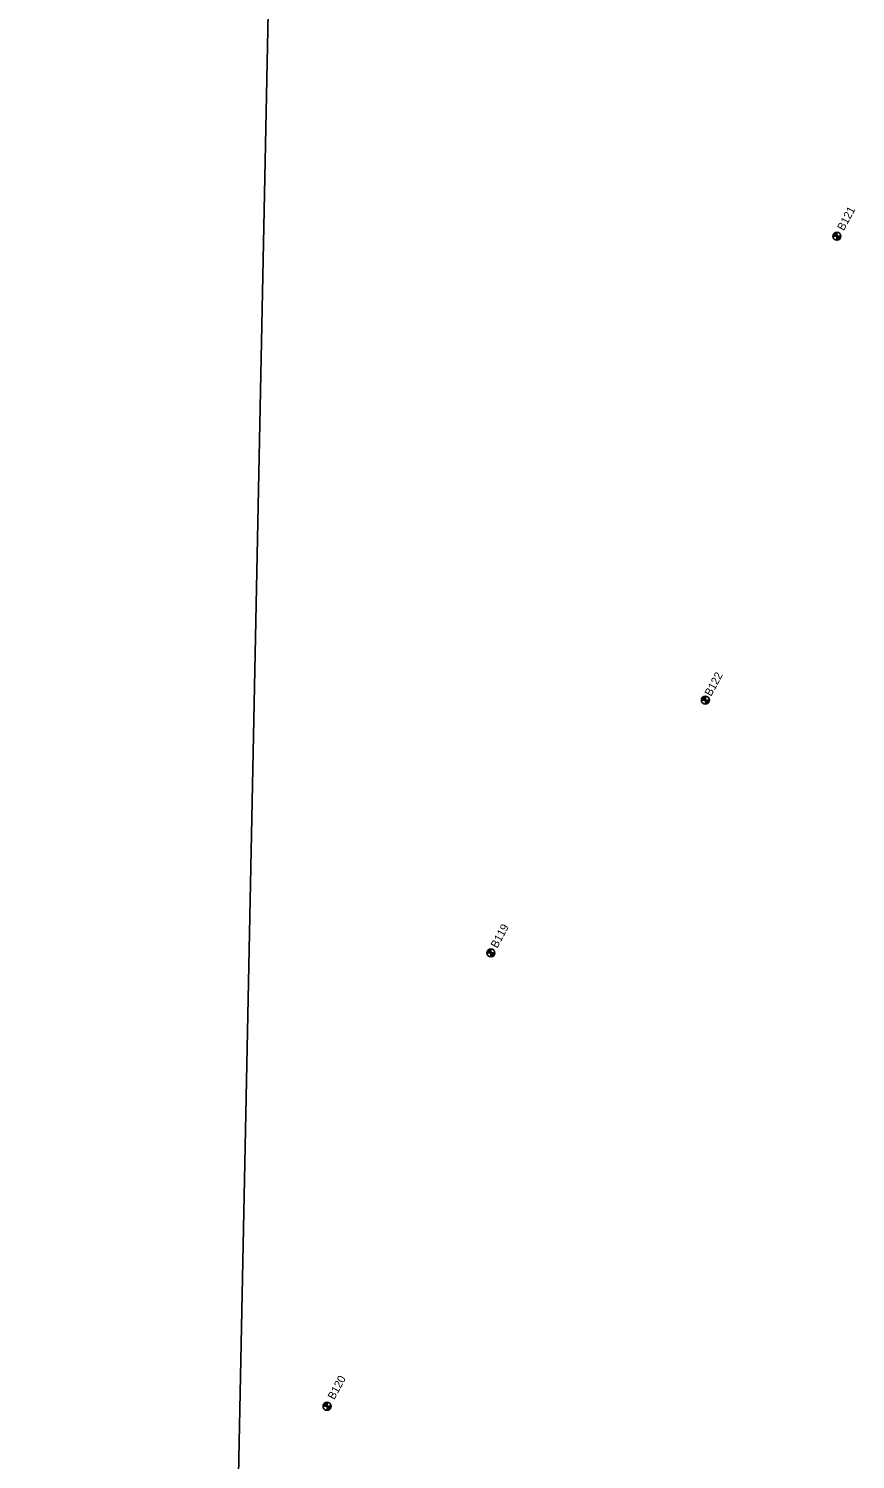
# Model space of a CAD drawing. Extents: x 345549 to 379569, y 127949 to 230467.
# Drawn here: x 355372 to 356405, y 194223 to 196011 of the extents above; entities that cross this region are included whole.
import ezdxf

# ---------------------------------------------------------------- set-up
doc = ezdxf.new("R2010")
doc.units = 0
for name, color, linetype in [('E_RDWY', 7, 'Continuous'), ('E_SOIL_BORE1 [KAPUR_CADDS_LEVELS]', 7, 'Continuous'), ('E_SOIL_BORE2 [KAPUR_CADDS_LEVELS]', 7, 'Continuous'), ('P_MARK', 7, 'Continuous')]:
    doc.layers.add(name, color=color, linetype=linetype)

msp = doc.modelspace()

# ---------------------------------------------------------------- linework, layer by layer
at = {"layer": 'E_RDWY'}
msp.add_line((355372.5, 181177.5), (356094.5, 217027.6), dxfattribs=at)
at = {"layer": 'P_MARK'}
for p, q in [((356377.4, 195752), (356387.4, 195752)), ((356382.4, 195757), (356382.4, 195747)), ((356213, 195172.4), (356223, 195172.4)), ((356218, 195177.4), (356218, 195167.4)), ((355945.1, 194856.3), (355955.1, 194856.3)), ((355950.1, 194861.3), (355950.1, 194851.3)), ((355740.3, 194289.7), (355750.3, 194289.7)), ((355745.3, 194294.7), (355745.3, 194284.7))]:
    msp.add_line(p, q, dxfattribs=at)
for centre in [(356382.4, 195752), (356218, 195172.4), (355950.1, 194856.3), (355745.3, 194289.7)]:
    msp.add_circle(centre, 5, dxfattribs=at)
for centre, radius, start, end in [((356382.4, 195752), 4.5, 89.9869, 179.9869), ((356382.4, 195752), 4, 89.9869, 179.9869), ((356382.4, 195752), 3.5, 89.9869, 179.9869), ((356382.4, 195752), 3, 89.9869, 179.9869), ((356382.4, 195752), 2.5, 89.9869, 179.9869), ((356382.4, 195752), 2, 89.9869, 179.9869), ((356382.4, 195752), 1.5, 89.9869, 179.9869), ((356382.4, 195752), 1, 89.9869, 179.9869), ((356382.4, 195752), 0.5, 89.9869, 179.9869), ((356382.4, 195752), 4.5, 269.9869, 359.9869), ((356382.4, 195752), 4, 269.9869, 359.9869), ((356382.4, 195752), 3.5, 269.9869, 359.9869), ((356382.4, 195752), 3, 269.9869, 359.9869), ((356382.4, 195752), 2.5, 269.9869, 359.9869), ((356382.4, 195752), 2, 269.9869, 359.9869), ((356382.4, 195752), 1.5, 269.9869, 359.9869), ((356382.4, 195752), 1, 269.9869, 359.9869), ((356382.4, 195752), 0.5, 269.9869, 359.9869), ((356218, 195172.4), 4.5, 89.9869, 179.9869), ((356218, 195172.4), 4, 89.9869, 179.9869), ((356218, 195172.4), 3.5, 89.9869, 179.9869), ((356218, 195172.4), 3, 89.9869, 179.9869), ((356218, 195172.4), 2.5, 89.9869, 179.9869), ((356218, 195172.4), 2, 89.9869, 179.9869), ((356218, 195172.4), 1.5, 89.9869, 179.9869), ((356218, 195172.4), 1, 89.9869, 179.9869), ((356218, 195172.4), 0.5, 89.9869, 179.9869), ((356218, 195172.4), 4.5, 269.9869, 359.9869), ((356218, 195172.4), 4, 269.9869, 359.9869), ((356218, 195172.4), 3.5, 269.9869, 359.9869), ((356218, 195172.4), 3, 269.9869, 359.9869), ((356218, 195172.4), 2.5, 269.9869, 359.9869), ((356218, 195172.4), 2, 269.9869, 359.9869), ((356218, 195172.4), 1.5, 269.9869, 359.9869), ((356218, 195172.4), 1, 269.9869, 359.9869), ((356218, 195172.4), 0.5, 269.9869, 359.9869), ((355950.1, 194856.3), 4.5, 89.9869, 179.9869), ((355950.1, 194856.3), 4, 89.9869, 179.9869), ((355950.1, 194856.3), 3.5, 89.9869, 179.9869), ((355950.1, 194856.3), 3, 89.9869, 179.9869), ((355950.1, 194856.3), 2.5, 89.9869, 179.9869), ((355950.1, 194856.3), 2, 89.9869, 179.9869), ((355950.1, 194856.3), 1.5, 89.9869, 179.9869), ((355950.1, 194856.3), 1, 89.9869, 179.9869), ((355950.1, 194856.3), 0.5, 89.9869, 179.9869), ((355950.1, 194856.3), 4.5, 269.9869, 359.9869), ((355950.1, 194856.3), 4, 269.9869, 359.9869), ((355950.1, 194856.3), 3.5, 269.9869, 359.9869), ((355950.1, 194856.3), 3, 269.9869, 359.9869), ((355950.1, 194856.3), 2.5, 269.9869, 359.9869), ((355950.1, 194856.3), 2, 269.9869, 359.9869), ((355950.1, 194856.3), 1.5, 269.9869, 359.9869), ((355950.1, 194856.3), 1, 269.9869, 359.9869), ((355950.1, 194856.3), 0.5, 269.9869, 359.9869), ((355745.3, 194289.7), 4.5, 89.9869, 179.9869), ((355745.3, 194289.7), 4, 89.9869, 179.9869), ((355745.3, 194289.7), 3.5, 89.9869, 179.9869), ((355745.3, 194289.7), 3, 89.9869, 179.9869), ((355745.3, 194289.7), 2.5, 89.9869, 179.9869), ((355745.3, 194289.7), 2, 89.9869, 179.9869), ((355745.3, 194289.7), 1.5, 89.9869, 179.9869), ((355745.3, 194289.7), 1, 89.9869, 179.9869), ((355745.3, 194289.7), 0.5, 89.9869, 179.9869), ((355745.3, 194289.7), 4.5, 269.9869, 359.9869), ((355745.3, 194289.7), 4, 269.9869, 359.9869), ((355745.3, 194289.7), 3.5, 269.9869, 359.9869), ((355745.3, 194289.7), 3, 269.9869, 359.9869), ((355745.3, 194289.7), 2.5, 269.9869, 359.9869), ((355745.3, 194289.7), 2, 269.9869, 359.9869), ((355745.3, 194289.7), 1.5, 269.9869, 359.9869), ((355745.3, 194289.7), 1, 269.9869, 359.9869), ((355745.3, 194289.7), 0.5, 269.9869, 359.9869)]:
    msp.add_arc(centre, radius, start, end, dxfattribs=at)

# ---------------------------------------------------------------- texts
at = {"layer": 'E_SOIL_BORE1 [KAPUR_CADDS_LEVELS]'}
for s, p in [('B121', (356390.9, 195758.2)), ('B122', (356225.2, 195176.3))]:
    msp.add_text(s, height=10, rotation=61.5935, dxfattribs=at).set_placement(p)
at = {"layer": 'E_SOIL_BORE2 [KAPUR_CADDS_LEVELS]'}
for s, p in [('B119', (355957.9, 194861.5)), ('B120', (355754.3, 194297.2))]:
    msp.add_text(s, height=10, rotation=61.5935, dxfattribs=at).set_placement(p)

doc.saveas('drawing.dxf')
